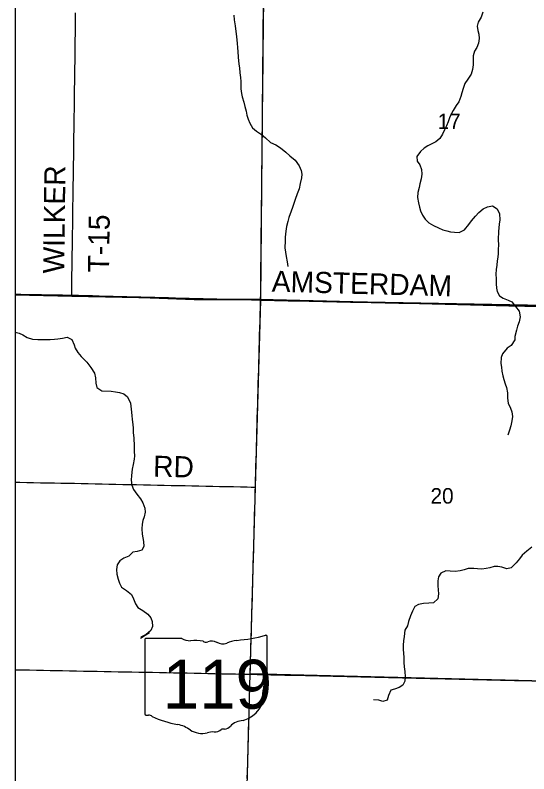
# Model space of a CAD drawing. Extents: x 0 to 34, y 0 to 22.
# Drawn here: x 2.1 to 3.484, y 15.194 to 17.239 of the extents above; entities that cross this region are included whole.
import ezdxf

# ---------------------------------------------------------------- set-up
doc = ezdxf.new("R2010")
doc.units = 0
for name, color, linetype in [('GM_X_Corporation', 7, 'Continuous'), ('GM_X_County_Road', 7, 'Continuous'), ('GM_X_County_Road_Text', 7, 'Continuous'), ('GM_X_Minor_River', 7, 'Continuous'), ('GM_X_Section_Text', 7, 'Continuous'), ('GM_X_State_Location', 7, 'Continuous'), ('GM_X_State_Route', 7, 'Continuous'), ('GM_X_State_Shield', 7, 'Continuous'), ('GM_X_Township_Road', 7, 'Continuous'), ('GM_X_Township_Road_Text', 7, 'Continuous')]:
    doc.layers.add(name, color=color, linetype=linetype)

msp = doc.modelspace()

# ---------------------------------------------------------------- linework, layer by layer
at = {"layer": 'GM_X_Corporation'}
for points in [[(8.9, 20.9), (2.1, 20.9), (2.1, 14.1), (7.7244, 14.1)], [(3.5996, 19.4692), (2.7976, 19.484), (2.7779, 19.4843), (2.1, 19.4964), (2.1, 16.485), (2.253, 16.4822), (2.4333, 16.478), (2.4403, 16.4778), (2.5826, 16.473), (2.7595, 16.4724), (3.1897, 16.4617), (3.4295, 16.4557), (3.687, 16.4502), (3.6948, 16.4501), (3.7682, 16.4494), (4.2697, 16.4379), (4.8738, 16.4249)], [(4.8738, 16.4249), (4.2697, 16.4379), (3.7682, 16.4494), (3.6948, 16.4501), (3.687, 16.4502), (3.4295, 16.4557), (3.1897, 16.4617), (2.7595, 16.4724), (2.5826, 16.473), (2.4403, 16.4778), (2.4333, 16.478), (2.253, 16.4822), (2.1, 16.485), (2.1, 14.1), (7.7244, 14.1)]]:
    msp.add_lwpolyline(points, dxfattribs=at)
for points in [[(3.785, 17.4549), (3.7672, 16.4521), (2.7618, 16.4707), (2.771, 17.4824)], [(2.7618, 16.4707), (3.7672, 16.4521), (3.745, 15.438), (2.7333, 15.4639)], [(3.745, 15.438), (3.7208, 14.432), (2.7064, 14.4541), (2.7333, 15.4639)]]:
    msp.add_lwpolyline(points, close=True, dxfattribs=at)
at = {"layer": 'GM_X_County_Road'}
for points in [[(2.1, 16.4873), (2.1153, 16.487), (2.1339, 16.4867), (2.1526, 16.4864), (2.1712, 16.4861), (2.1899, 16.4858), (2.2085, 16.4855), (2.2271, 16.4851), (2.2397, 16.4849), (2.2522, 16.4847), (2.2708, 16.4842), (2.2894, 16.4837), (2.3081, 16.4832), (2.3267, 16.4827), (2.3453, 16.4822), (2.364, 16.4817), (2.3826, 16.4813), (2.4012, 16.4808), (2.4199, 16.4803), (2.4385, 16.4798), (2.4572, 16.4793), (2.4758, 16.4788), (2.4944, 16.4783), (2.5131, 16.4778), (2.5317, 16.4773), (2.5503, 16.4768), (2.569, 16.4763), (2.5876, 16.4758), (2.6062, 16.4753), (2.6249, 16.4748), (2.6435, 16.4743), (2.6621, 16.4738), (2.6808, 16.4733), (2.6994, 16.4729), (2.718, 16.4724), (2.7367, 16.4719), (2.7489, 16.4715), (2.7612, 16.4712), (2.7798, 16.4708), (2.7984, 16.4704), (2.8171, 16.47), (2.8357, 16.4696), (2.8543, 16.4692), (2.873, 16.4688), (2.8916, 16.4684), (2.9103, 16.468), (2.9289, 16.4676), (2.9475, 16.4672), (2.9662, 16.4668), (2.9848, 16.4664), (3.0034, 16.466), (3.0221, 16.4657), (3.0407, 16.4653), (3.0593, 16.4649), (3.078, 16.4645), (3.0966, 16.4641), (3.1152, 16.4637), (3.1339, 16.4633), (3.1525, 16.4629), (3.1711, 16.4625), (3.1898, 16.4621), (3.2084, 16.4617), (3.227, 16.4613), (3.2457, 16.4609), (3.2555, 16.4607), (3.2652, 16.4605), (3.2839, 16.4601), (3.3025, 16.4597), (3.3211, 16.4593), (3.3398, 16.4589), (3.3584, 16.4585), (3.377, 16.4581), (3.3957, 16.4577), (3.4143, 16.4573), (3.4329, 16.4569), (3.4516, 16.4565), (3.4702, 16.4561), (3.4889, 16.4558)], [(2.1, 15.9802), (2.1123, 15.98), (2.131, 15.9796), (2.1496, 15.9793), (2.1682, 15.9789), (2.1869, 15.9786), (2.2055, 15.9782), (2.2231, 15.9779), (2.2408, 15.9776), (2.2594, 15.9772), (2.278, 15.9768), (2.2967, 15.9764), (2.3153, 15.976), (2.3339, 15.9756), (2.3526, 15.9752), (2.3712, 15.9748), (2.3898, 15.9744), (2.4085, 15.974), (2.4271, 15.9737), (2.4457, 15.9733), (2.4644, 15.9729), (2.483, 15.9725), (2.5016, 15.9721), (2.5203, 15.9717), (2.5389, 15.9713), (2.5576, 15.9709), (2.5762, 15.9705), (2.5948, 15.9701), (2.6135, 15.9697), (2.6321, 15.9693), (2.6507, 15.969), (2.6694, 15.9686), (2.688, 15.9682), (2.7066, 15.9678), (2.7253, 15.9674), (2.7362, 15.9672), (2.7471, 15.9669)]]:
    msp.add_lwpolyline(points, dxfattribs=at)
at = {"layer": 'GM_X_Minor_River'}
for points in [[(3.3603, 17.2473), (3.3551, 17.2341), (3.3472, 17.2206), (3.345, 17.21), (3.3463, 17.1978), (3.3487, 17.1882), (3.3496, 17.1768), (3.3478, 17.1639), (3.3438, 17.1518), (3.3375, 17.1421), (3.3342, 17.1296), (3.3335, 17.1186), (3.334, 17.1057), (3.3322, 17.0928), (3.3281, 17.0803), (3.3191, 17.0672), (3.3117, 17.0548), (3.3068, 17.0413), (3.3035, 17.0299), (3.301, 17.0201), (3.295, 17.0058), (3.2883, 16.9957), (3.2801, 16.9822), (3.2749, 16.9724), (3.2705, 16.9622), (3.2669, 16.9517), (3.2617, 16.9411), (3.2569, 16.9302), (3.2514, 16.9182), (3.2443, 16.9073), (3.2331, 16.8977), (3.2223, 16.8926), (3.2116, 16.8872), (3.202, 16.8809), (3.1919, 16.872), (3.1821, 16.8582), (3.183, 16.846), (3.1903, 16.8356), (3.195, 16.8229), (3.1955, 16.8107), (3.1937, 16.7982)], [(2.6891, 17.2395), (2.6903, 17.2265), (2.6926, 17.2105), (2.6961, 17.1811), (2.6976, 17.1643), (2.6992, 17.151), (2.6998, 17.1415), (2.7006, 17.1266), (2.7025, 17.1072), (2.7041, 17.0976), (2.7053, 17.0835), (2.707, 17.071), (2.7079, 17.0603), (2.7076, 17.0504), (2.7082, 17.0405), (2.7098, 17.0283), (2.7111, 17.0188), (2.7157, 17.0046), (2.7185, 16.9931), (2.722, 16.9805), (2.7244, 16.9694), (2.7273, 16.9591), (2.7323, 16.9483), (2.7396, 16.9356), (2.7501, 16.9266), (2.7639, 16.9179), (2.7747, 16.9086), (2.7877, 16.8957), (2.8023, 16.8901), (2.8151, 16.8818), (2.8292, 16.8701), (2.84, 16.8599), (2.8541, 16.8482), (2.8652, 16.8335)], [(2.8652, 16.8335), (2.8702, 16.8205), (2.8719, 16.8105), (2.8713, 16.8007), (2.8679, 16.7855), (2.865, 16.7715), (2.8601, 16.7576), (2.8541, 16.7421), (2.8504, 16.7319), (2.8468, 16.721), (2.8439, 16.7108), (2.8371, 16.6935), (2.8342, 16.6829), (2.8305, 16.6697), (2.8287, 16.6572), (2.8276, 16.6412), (2.827, 16.6314), (2.8269, 16.6123), (2.8285, 16.6001), (2.8302, 16.5887), (2.8325, 16.5746), (2.8341, 16.562)], [(3.1937, 16.7982), (3.1904, 16.7846), (3.1886, 16.7744), (3.1849, 16.7615), (3.1838, 16.7479), (3.1862, 16.733), (3.189, 16.7219), (3.1922, 16.7123), (3.1972, 16.7001), (3.2042, 16.6893), (3.2142, 16.6799), (3.2273, 16.672), (3.2404, 16.666), (3.2521, 16.6604), (3.2626, 16.6575), (3.2725, 16.6554), (3.2838, 16.654), (3.2959, 16.6537), (3.3105, 16.6602), (3.3226, 16.6747), (3.3296, 16.6852), (3.3398, 16.6979), (3.3487, 16.7076), (3.3607, 16.7172), (3.3726, 16.7226), (3.3855, 16.7254), (3.3986, 16.7171), (3.4044, 16.7037), (3.4056, 16.688), (3.4038, 16.6759), (3.4028, 16.6657), (3.4018, 16.6562), (3.4014, 16.6345), (3.4018, 16.6197), (3.4012, 16.6087), (3.4009, 16.5965), (3.3999, 16.5871), (3.3982, 16.5772), (3.3972, 16.5651), (3.3958, 16.5541), (3.3951, 16.5412), (3.3956, 16.5286), (3.396, 16.5149), (3.3969, 16.5035), (3.3986, 16.494), (3.4044, 16.4828), (3.4149, 16.4761), (3.4281, 16.4709), (3.4378, 16.4661), (3.4482, 16.4537), (3.4574, 16.4413), (3.4605, 16.4264), (3.4582, 16.4124), (3.4534, 16.4011), (3.4502, 16.3902), (3.4464, 16.3735), (3.4458, 16.364), (3.436, 16.3491), (3.4255, 16.3413), (3.4131, 16.326), (3.4091, 16.3162), (3.4083, 16.3007), (3.4104, 16.29), (3.4113, 16.2793), (3.4136, 16.2667), (3.4165, 16.2572), (3.42, 16.2457), (3.4236, 16.2357), (3.4267, 16.2216), (3.4267, 16.2064), (3.4283, 16.1934), (3.4344, 16.1796), (3.4384, 16.17), (3.44, 16.1571), (3.4378, 16.1453), (3.4353, 16.1321), (3.4316, 16.1204), (3.4275, 16.1072)], [(2.1, 16.3848), (2.1106, 16.3819), (2.1203, 16.3771), (2.1327, 16.3707), (2.1462, 16.3662), (2.1606, 16.3651), (2.1701, 16.3653), (2.183, 16.3654), (2.194, 16.3648), (2.2058, 16.3656), (2.2153, 16.3666), (2.2279, 16.3689), (2.24, 16.3713), (2.2524, 16.365), (2.2589, 16.3508), (2.2617, 16.3412), (2.2691, 16.3296), (2.2779, 16.3188), (2.2932, 16.304), (2.3038, 16.2893), (2.3137, 16.2739), (2.3165, 16.262), (2.3177, 16.2472), (2.3197, 16.2357), (2.3335, 16.2263), (2.3582, 16.2258), (2.3706, 16.224), (2.3808, 16.2222), (2.3925, 16.2189), (2.4022, 16.2107), (2.4105, 16.193)], [(2.4105, 16.193), (2.4128, 16.177), (2.4147, 16.1599), (2.4156, 16.1492), (2.4168, 16.1355), (2.4177, 16.1256), (2.4183, 16.1146), (2.4194, 16.0986), (2.4205, 16.0784), (2.4209, 16.0628), (2.421, 16.0514), (2.4204, 16.0419), (2.4182, 16.0283), (2.4153, 16.0151), (2.413, 15.998), (2.4123, 15.9855), (2.4143, 15.9718), (2.419, 15.9603), (2.4274, 15.9483), (2.4378, 15.9355), (2.4443, 15.9248), (2.4497, 15.9098), (2.4502, 15.8995), (2.4473, 15.8867), (2.444, 15.8769), (2.4423, 15.8667), (2.4412, 15.8542), (2.4421, 15.8401), (2.4441, 15.8301), (2.4458, 15.8199), (2.4462, 15.8069), (2.4411, 15.7968), (2.4285, 15.7933), (2.4171, 15.7912), (2.4058, 15.7805), (2.3924, 15.7758), (2.3817, 15.7685), (2.375, 15.7576), (2.3728, 15.7451), (2.374, 15.7322), (2.3771, 15.7192), (2.381, 15.7077), (2.3865, 15.6973), (2.3999, 15.6879), (2.413, 15.6774), (2.4184, 15.6658), (2.4238, 15.6524), (2.4308, 15.6428), (2.4439, 15.6345), (2.4573, 15.6247), (2.4658, 15.6142), (2.469, 15.6043), (2.4702, 15.591), (2.4658, 15.5801), (2.4526, 15.5693), (2.4385, 15.5624)], [(3.4916, 15.8048), (3.4781, 15.7945), (3.4661, 15.7834), (3.4583, 15.7737), (3.4493, 15.7625), (3.4361, 15.7491), (3.4243, 15.7467), (3.4108, 15.7512), (3.4006, 15.753), (3.3903, 15.7525), (3.3789, 15.7493), (3.3693, 15.7472), (3.3568, 15.7456), (3.3454, 15.7463), (3.3356, 15.7476), (3.3208, 15.7472), (3.3097, 15.7441), (3.299, 15.7413), (3.2857, 15.7393), (3.2721, 15.7404), (3.2599, 15.741), (3.2469, 15.7349), (3.2402, 15.7251), (3.2385, 15.7142), (3.2385, 15.7009), (3.2394, 15.6902), (3.2403, 15.6792), (3.2385, 15.6659), (3.2273, 15.6552), (3.2147, 15.6543), (3.2003, 15.6531), (3.1866, 15.6504), (3.1766, 15.6453), (3.1706, 15.6321), (3.1646, 15.6197), (3.1598, 15.605), (3.1565, 15.5933), (3.1497, 15.5817), (3.1482, 15.5643), (3.1461, 15.5526), (3.1454, 15.5408), (3.1452, 15.5305), (3.1457, 15.518), (3.1466, 15.5085), (3.1474, 15.4937), (3.1483, 15.4822), (3.1499, 15.4697), (3.1503, 15.4552), (3.1493, 15.4438), (3.1441, 15.4333), (3.1345, 15.4267), (3.1215, 15.4225), (3.1119, 15.4193), (3.1055, 15.405), (3.1022, 15.3929), (3.0908, 15.3886), (3.0795, 15.3923)], [(2.4618, 15.574), (2.45, 15.5666), (2.4373, 15.5592)], [(3.0795, 15.3923), (3.0654, 15.3933)]]:
    msp.add_lwpolyline(points, dxfattribs=at)
at = {"layer": 'GM_X_State_Route'}
for points in [[(2.7612, 16.4712), (2.7614, 16.4899), (2.7616, 16.5085), (2.7617, 16.5271), (2.7619, 16.5458), (2.7621, 16.5644), (2.7623, 16.5831), (2.7625, 16.6017), (2.7627, 16.6203), (2.7629, 16.639), (2.7631, 16.6576), (2.7633, 16.6763), (2.7635, 16.6949), (2.7637, 16.7136), (2.7639, 16.7322), (2.7641, 16.7508), (2.7643, 16.7695), (2.7645, 16.7881), (2.7647, 16.8068), (2.7649, 16.8254), (2.7651, 16.844), (2.7653, 16.8627), (2.7655, 16.8813), (2.7657, 16.9), (2.7659, 16.9186), (2.766, 16.9372), (2.7662, 16.9559), (2.7664, 16.9666), (2.7665, 16.9774), (2.7667, 16.996), (2.7669, 17.0146), (2.7671, 17.0333), (2.7673, 17.0519), (2.7675, 17.0706), (2.7677, 17.0892), (2.7679, 17.1079), (2.7681, 17.1265), (2.7683, 17.1451), (2.7685, 17.1638), (2.7688, 17.1824), (2.769, 17.2011), (2.7692, 17.2197), (2.7694, 17.2383), (2.7696, 17.257)], [(2.7332, 15.4626), (2.7337, 15.4812), (2.7342, 15.4999), (2.7347, 15.5185), (2.7352, 15.5371), (2.7358, 15.5558), (2.7363, 15.5744), (2.7368, 15.593), (2.7373, 15.6117), (2.7378, 15.6303), (2.7383, 15.6489), (2.7389, 15.6676), (2.7394, 15.6862), (2.7399, 15.7049), (2.7404, 15.7235), (2.7409, 15.7421), (2.7414, 15.7608), (2.7419, 15.7794), (2.7425, 15.798), (2.743, 15.8167), (2.7435, 15.8353), (2.744, 15.8539), (2.7445, 15.8726), (2.745, 15.8912), (2.7456, 15.9098), (2.7461, 15.9285), (2.7466, 15.9471), (2.7469, 15.957), (2.7471, 15.9669), (2.7477, 15.9856), (2.7482, 16.0042), (2.7487, 16.0228), (2.7492, 16.0415), (2.7497, 16.0601), (2.7502, 16.0787), (2.7508, 16.0974), (2.7513, 16.116), (2.7518, 16.1346), (2.7523, 16.1533), (2.7528, 16.1719), (2.7534, 16.1905), (2.7539, 16.2092), (2.7544, 16.2278), (2.7549, 16.2464), (2.7554, 16.2651), (2.756, 16.2837), (2.7565, 16.3024), (2.757, 16.321), (2.7575, 16.3396), (2.758, 16.3583), (2.7585, 16.3769), (2.7591, 16.3955), (2.7596, 16.4142), (2.7601, 16.4328), (2.7606, 16.4514), (2.7609, 16.4613), (2.7612, 16.4712)], [(2.1, 15.4746), (2.1014, 15.4746), (2.12, 15.4743), (2.1387, 15.4739), (2.1573, 15.4735), (2.1759, 15.4732), (2.1946, 15.4728), (2.2112, 15.4725), (2.2279, 15.4722), (2.2466, 15.4718), (2.2652, 15.4715), (2.2838, 15.4711), (2.3025, 15.4708), (2.3211, 15.4704), (2.3397, 15.47), (2.3584, 15.4697), (2.377, 15.4693), (2.3957, 15.469), (2.4143, 15.4686), (2.4329, 15.4683), (2.4516, 15.4679), (2.4702, 15.4676), (2.4888, 15.4672), (2.5075, 15.4669), (2.5261, 15.4665), (2.5447, 15.4662), (2.5634, 15.4658), (2.582, 15.4654), (2.6006, 15.4651), (2.6193, 15.4647), (2.6379, 15.4644), (2.6565, 15.464), (2.6752, 15.4637), (2.6938, 15.4633), (2.7124, 15.463), (2.7228, 15.4628), (2.7332, 15.4626), (2.7518, 15.4622), (2.7704, 15.4617), (2.7891, 15.4613), (2.8077, 15.4609), (2.8264, 15.4604), (2.845, 15.46), (2.8636, 15.4596), (2.8823, 15.4591), (2.9009, 15.4587), (2.9195, 15.4582), (2.9382, 15.4578), (2.9568, 15.4574), (2.9754, 15.4569), (2.9941, 15.4565), (3.0127, 15.4561), (3.0313, 15.4557), (3.05, 15.4552), (3.0686, 15.4548), (3.0872, 15.4544), (3.1059, 15.4539), (3.1245, 15.4535), (3.1431, 15.4531), (3.1618, 15.4526), (3.1804, 15.4522), (3.1991, 15.4518), (3.2177, 15.4513), (3.2288, 15.4511), (3.2398, 15.4508), (3.2585, 15.4504), (3.2771, 15.45), (3.2957, 15.4495), (3.3144, 15.4491), (3.333, 15.4486), (3.3516, 15.4482), (3.3703, 15.4478), (3.3889, 15.4473), (3.4075, 15.4469), (3.4262, 15.4465), (3.4448, 15.446), (3.4634, 15.4456), (3.4821, 15.4452), (3.5007, 15.4447)], [(2.7253, 15.1813), (2.7259, 15.1999), (2.7264, 15.2186), (2.7269, 15.2372), (2.7274, 15.2558), (2.7279, 15.2745), (2.7285, 15.2931), (2.729, 15.3117), (2.7295, 15.3304), (2.73, 15.349), (2.7305, 15.3676), (2.7311, 15.3863), (2.7316, 15.4049), (2.7321, 15.4235), (2.7326, 15.4422), (2.7329, 15.4524), (2.7332, 15.4626)]]:
    msp.add_lwpolyline(points, dxfattribs=at)
at = {"layer": 'GM_X_State_Shield'}
for p, q in [((2.4492, 15.5557), (2.4492, 15.3556)), ((2.549, 15.5591), (2.4525, 15.5591)), ((2.7788, 15.4594), (2.7788, 15.5641)), ((2.7788, 15.4594), (2.7788, 15.4594))]:
    msp.add_line(p, q, dxfattribs=at)
for centre, major_axis, start_param, end_param in [((2.6614, 15.832), (0.3495, 0), 4.814394, 5.042369), ((2.7752, 15.5645), (0.00367, 0), 6.141152, 7.989035), ((2.453, 15.5561), (0.00382, 0), 1.712693, 3.28349), ((2.572, 15.5824), (0.037, 0), 4.042523, 4.731795), ((2.5843, 15.4468), (0.133, 0), 1.404758, 1.657858), ((2.6144, 15.5572), (0.0107, 0), 3.836095, 5.185415), ((2.6301, 15.534), (0.0222, 0), 0.950623, 2.079405), ((2.6588, 15.5658), (0.0267, 0), 4.081561, 5.145723), ((2.706, 15.498), (0.0703, 0), 1.699011, 2.107814), ((2.778, 15.4517), (0.00568, 0), 1.883978, 3.671073), ((2.7418, 15.4385), (0.0341, 0), 5.934695, 6.695948), ((2.7749, 15.459), (0.00393, 0), 5.05454, 6.418171), ((2.792, 15.4156), (0.0248, 0), 2.387724, 3.262537), ((2.681, 15.4023), (0.0874, 0), 5.101752, 6.440018), ((2.453, 15.3551), (0.00385, 0), 3.00124, 4.508301), ((2.4536, 15.3756), (0.0294, 0), 4.665946, 4.897461), ((2.4596, 15.344), (0.0106, 0), 0.519207, 1.627899), ((2.5935, 15.5238), (0.2524, 0), 4.195997, 4.488961), ((2.5182, 15.2657), (0.079, 0), 0.823519, 1.323587), ((2.6572, 15.3362), (0.0282, 0), 4.937069, 5.64225), ((2.7179, 15.2994), (0.0479, 0), 1.647645, 2.488434), ((2.6036, 15.343), (0.0501, 0), 4.026481, 4.996735), ((2.6326, 15.2738), (0.0412, 0), 1.495662, 1.94098), ((2.6362, 15.3281), (0.0267, 0), 4.691044, 5.507374), ((2.6604, 15.3087), (0.00752, 0), 1.147584, 2.315152)]:
    msp.add_ellipse(centre, major_axis=major_axis, ratio=0.8, start_param=start_param, end_param=end_param, dxfattribs=at)
at = {"layer": 'GM_X_Township_Road'}
msp.add_lwpolyline([(2.2522, 16.4847), (2.2524, 16.5022), (2.2527, 16.5209), (2.253, 16.5395), (2.2532, 16.5582), (2.2535, 16.5768), (2.2538, 16.5954), (2.2541, 16.6141), (2.2543, 16.6327), (2.2546, 16.6514), (2.2549, 16.67), (2.2552, 16.6886), (2.2554, 16.7073), (2.2557, 16.7259), (2.256, 16.7446), (2.2563, 16.7632), (2.2565, 16.7819), (2.2568, 16.8005), (2.2571, 16.8191), (2.2573, 16.8378), (2.2576, 16.8564), (2.2579, 16.8751), (2.2582, 16.8937), (2.2584, 16.9123), (2.2587, 16.931), (2.259, 16.9496), (2.2592, 16.9672), (2.2595, 16.9847), (2.2597, 17.0034), (2.26, 17.022), (2.2602, 17.0407), (2.2604, 17.0593), (2.2607, 17.0779), (2.2609, 17.0966), (2.2612, 17.1152), (2.2614, 17.1339), (2.2617, 17.1525), (2.2619, 17.1711), (2.2621, 17.1898), (2.2624, 17.2084), (2.2626, 17.2271), (2.2629, 17.2457)], dxfattribs=at)

# ---------------------------------------------------------------- texts
at = {"layer": 'GM_X_County_Road_Text'}
for s, rotation, p in [('AMSTERDAM', 358.4952, (2.7907, 16.4939)), ('RD', 359.0118, (2.4713, 15.9949))]:
    msp.add_text(s, height=0.05682, rotation=rotation, dxfattribs=at).set_placement(p)
at = {"layer": 'GM_X_Section_Text'}
for s, p in [('17', (3.238, 16.9322)), ('20', (3.2189, 15.9225))]:
    msp.add_text(s, height=0.04186, rotation=0, dxfattribs=at).set_placement(p)
at = {"layer": 'GM_X_State_Location'}
msp.add_text('119', height=0.000189, rotation=0, dxfattribs=at).set_placement((2.5435, 15.4286))
for s in ['s', 'r']:
    msp.add_text(s, height=0.000189, dxfattribs=at).set_placement((2.6103, 15.4423))
at = {"layer": 'GM_X_State_Shield'}
msp.add_text('119', height=0.13184, dxfattribs=at).set_placement((2.4977, 15.3697))
at = {"layer": 'GM_X_Township_Road_Text'}
for s, rotation, p in [('WILKER', 89.2927, (2.232, 16.5427)), ('T-15', 89.2931, (2.3529, 16.5454))]:
    msp.add_text(s, height=0.05682, rotation=rotation, dxfattribs=at).set_placement(p)

doc.saveas('drawing.dxf')
